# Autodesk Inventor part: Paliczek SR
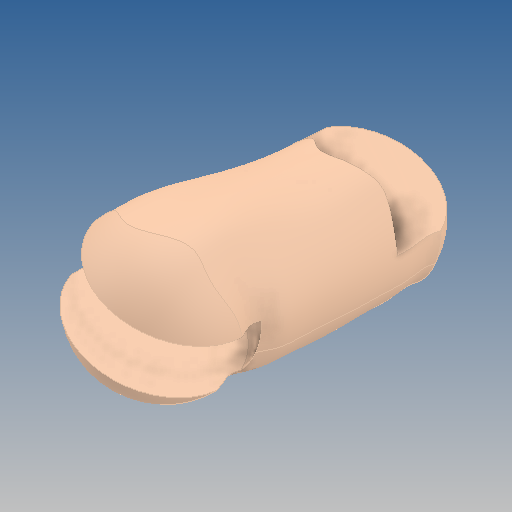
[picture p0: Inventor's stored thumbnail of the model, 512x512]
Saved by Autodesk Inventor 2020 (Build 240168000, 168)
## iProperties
Created: 2019-10
Part Number: Paliczek SR
Material: GFRP
Document SubType Name: Modeling
Designer: yello
Density: 1.75 g/cm^3
Appearance: Default
Author: yello
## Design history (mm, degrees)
feature "Paliczek SR"
body "Solid1"
